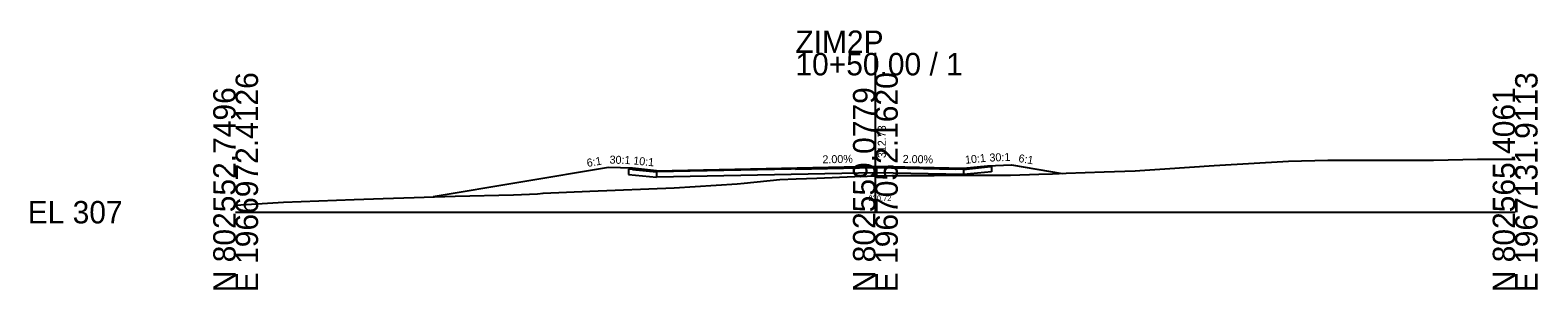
# Model space of a CAD drawing. Extents: x 1950845 to 1951408, y 736831 to 740365.
# Drawn here: x 1950844.5 to 1951033.1, y 737331.5 to 737363.9 of the extents above; entities that cross this region are included whole.
import ezdxf

# ---------------------------------------------------------------- set-up
doc = ezdxf.new("R2010")
doc.units = 0
for name, color, linetype in [('RD_GPK_XS_Cell', 7, 'Continuous'), ('RD_XS_Base', 7, 'Continuous'), ('RD_XS_EarthShd', 7, 'Continuous'), ('RD_XS_ExGround', 7, 'Continuous'), ('RD_XS_Pave', 7, 'Continuous'), ('RD_XS_PaveOvlay', 7, 'Continuous'), ('RD_XS_TieSlope', 7, 'Continuous'), ('RD_XS_TX_Elev_EX', 7, 'Continuous'), ('RD_XS_TX_Elev_PR', 7, 'Continuous'), ('RD_XS_TX_Slope', 7, 'Continuous')]:
    doc.layers.add(name, color=color, linetype=linetype)

msp = doc.modelspace()

# ---------------------------------------------------------------- linework, layer by layer
at = {"layer": 'RD_GPK_XS_Cell'}
for p, q in [((1950950.22, 737341.19), (1950950.22, 737361.08)), ((1950870.22, 737341.19), (1950950.22, 737341.19)), ((1950950.22, 737341.19), (1951030.22, 737341.19))]:
    msp.add_line(p, q, dxfattribs=at)
at = {"layer": 'RD_XS_Base'}
for points in [[(1950922.86, 737346.22), (1950919.86, 737346.52), (1950919.36, 737346.57)], [(1950919.36, 737346.57), (1950919.36, 737345.9)], [(1950919.36, 737345.9), (1950922.86, 737345.55)], [(1950922.86, 737346.22), (1950922.86, 737345.55)], [(1950961.22, 737345.89), (1950950.22, 737346.1), (1950922.86, 737345.55)], [(1950940.22, 737346.56), (1950950.22, 737346.76), (1950960.22, 737346.56)], [(1950961.22, 737346.54), (1950964.22, 737346.84), (1950964.72, 737346.89)], [(1950961.22, 737346.54), (1950961.22, 737345.88)], [(1950964.72, 737346.23), (1950961.22, 737345.88)], [(1950964.72, 737346.89), (1950964.72, 737346.23)]]:
    msp.add_lwpolyline(points, dxfattribs=at)
at = {"layer": 'RD_XS_EarthShd'}
for points in [[(1950919.86, 737346.67), (1950916.86, 737346.77)], [(1950964.22, 737347), (1950967.22, 737347.1)]]:
    msp.add_lwpolyline(points, dxfattribs=at)
at = {"layer": 'RD_XS_ExGround'}
msp.add_lwpolyline([(1950870.22, 737342.06), (1950876.22, 737342.44), (1950885.05, 737342.77), (1950888.66, 737342.9), (1950897.66, 737343.21), (1950904.96, 737343.37), (1950907.95, 737343.47), (1950908.69, 737343.57), (1950914.51, 737343.8), (1950925.05, 737344.23), (1950932.93, 737344.74), (1950933.79, 737344.83), (1950938.29, 737345.28), (1950940.31, 737345.36), (1950942.88, 737345.45), (1950947.66, 737345.66), (1950949.2, 737345.71), (1950950.22, 737345.73), (1950952.27, 737345.78), (1950954.24, 737345.78), (1950957.58, 737345.78), (1950962.02, 737345.81), (1950967.12, 737345.81), (1950970.64, 737345.94), (1950972.38, 737346), (1950974.07, 737346.06), (1950978.82, 737346.23), (1950982.7, 737346.36), (1950983.29, 737346.39), (1950986.41, 737346.6), (1950992.59, 737347.04), (1951001.88, 737347.55), (1951006.81, 737347.67), (1951020.03, 737347.71), (1951025.5, 737347.82), (1951030.22, 737347.82)], dxfattribs=at)
at = {"layer": 'RD_XS_Pave'}
for points in [[(1950922.86, 737346.37), (1950919.86, 737346.67)], [(1950919.86, 737346.67), (1950919.86, 737346.52)], [(1950919.86, 737346.52), (1950922.86, 737346.22)], [(1950922.86, 737346.22), (1950922.86, 737346.37)], [(1950961.22, 737346.7), (1950964.22, 737347)], [(1950964.22, 737346.84), (1950961.22, 737346.54)], [(1950961.22, 737346.54), (1950961.22, 737346.7)], [(1950964.22, 737347), (1950964.22, 737346.84)]]:
    msp.add_lwpolyline(points, dxfattribs=at)
at = {"layer": 'RD_XS_PaveOvlay'}
for points in [[(1950922.86, 737346.37), (1950950.22, 737346.92), (1950961.22, 737346.7)], [(1950961.22, 737346.54), (1950950.22, 737346.76), (1950922.86, 737346.22)], [(1950922.86, 737346.37), (1950922.86, 737346.22)], [(1950961.22, 737346.7), (1950961.22, 737346.54)]]:
    msp.add_lwpolyline(points, dxfattribs=at)
at = {"layer": 'RD_XS_TieSlope'}
for points in [[(1950916.86, 737346.77), (1950894.92, 737343.12)], [(1950967.22, 737347.1), (1950973.59, 737346.04)]]:
    msp.add_lwpolyline(points, dxfattribs=at)

# ---------------------------------------------------------------- texts
at = {"layer": 'RD_GPK_XS_Cell'}
for s, p in [('ZIM2P', (1950940.22, 737361.08)), ('10+50.00 / 1', (1950940.22, 737358.28)), ('EL 307', (1950844.22, 737339.79))]:
    msp.add_text(s, height=2.8, dxfattribs=at).set_placement(p)
for s, p in [('E 1966972.4126', (1950873.02, 737331.19)), ('E 1967052.1620', (1950953.02, 737331.19)), ('E 1967131.9113', (1951033.02, 737331.19)), ('N 802552.7496', (1950870.22, 737331.19)), ('N 802559.0779', (1950950.22, 737331.19)), ('N 802565.4061', (1951030.22, 737331.19))]:
    msp.add_text(s, height=2.8, rotation=90, dxfattribs=at).set_placement(p)
at = {"layer": 'RD_XS_TX_Elev_EX'}
msp.add_text('220.72', height=0.7, dxfattribs=at).set_placement((1950949.35, 737342.58))
at = {"layer": 'RD_XS_TX_Elev_PR'}
msp.add_text('312.73', height=1, rotation=90, dxfattribs=at).set_placement((1950951.52, 737347.95))
at = {"layer": 'RD_XS_TX_Slope'}
for s, rotation, p in [('6:1', 9.4642, (1950914.21, 737346.84)), ('30:1', 358.0908, (1950916.97, 737347.27)), ('10:1', 354.2894, (1950919.91, 737347.17)), ('2.00%', 1.1458, (1950943.61, 737347.29)), ('2.00%', 358.8542, (1950953.63, 737347.35)), ('10:1', 5.7106, (1950961.48, 737347.23)), ('30:1', 1.9092, (1950964.5, 737347.51)), ('6:1', 350.5358, (1950968.06, 737347.47))]:
    msp.add_text(s, height=1, rotation=rotation, dxfattribs=at).set_placement(p)

doc.saveas('drawing.dxf')
